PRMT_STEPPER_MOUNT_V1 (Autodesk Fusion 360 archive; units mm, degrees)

design "PRMT_STEPPER_MOUNT_V1" references "23HS30-2904S-EGS50", "17HS13-0404S-MG5", "14HS13-0804S-PG14"
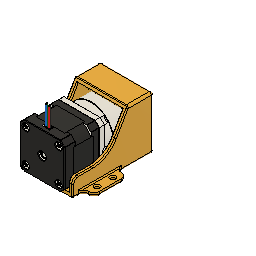
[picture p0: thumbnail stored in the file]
part number: 2026-08-30-19-16-32-664
part number: 2026-09-01-19-58-08-803
parameter "PLT_V" = 42
parameter "PLT_H" = 42
parameter "PLT_HOLE_DIA" = 3.3
parameter "TOL_HOLE_DIA" = 0.2
parameter "PLT_SIDE_H" = 5
parameter "PLT_SIDE_V" = 5
parameter "SHAFT_DIA" = 8
parameter "HEIGTH" = 76
parameter "PLT_HOLE_DIST" = 17.5
parameter "d23" = 5 (= "PLT_SIDE_V")
component_insert "Component Insert1"
component_insert "Component Insert2"
component_insert "Component Insert3"
as_built_joint "As-built1"
as_built_joint "As-built2"
position "Position1"
work_plane "WorkPlane1" AlongDistance 0 ExtraOffset 0
sketch "Sketch1" plane through (0, 0, -38.8) normal (0, 0, -1) x axis (-1, 0, 0)
  curve K1 (23.57, 21.92) -> (23.57, 21.92)
  curve K2 (-23.57, 21.92) -> (-23.57, 21.92)
  curve K3 (-23.57, -25.22) -> (-23.57, -25.22)
  curve K4 (23.57, -25.22) -> (23.57, -25.22)
  line L1 (-25, 25) -> (25, 25)
  line L2 (-25, -25) -> (-25, 25)
  line L3 (25, -25) -> (-25, -25)
  line L4 (25, 25) -> (25, -25)
  line L5 (-25, -25) -> (25, 25)
  line L6 (25, -25) -> (-25, 25)
  circle C1 centre (-17.5, 0) radius 1.75
  circle C2 centre (-23.57, 23.57) radius 1.65
  circle C3 centre (23.57, 23.57) radius 1.65
  circle C4 centre (-23.57, -23.57) radius 1.65
  circle C5 centre (0, 0) radius 8.75
  circle C6 centre (0, 0) radius 1.25
  point P1 (0, 0)
  point P2 (0, 0)
  point P19 (0, 0)
  point P20 (0, 0)
  point P3 (-17.5, 0)
  point P15 (25, 25)
  point P16 (-25, 25)
  point P18 (25, -25)
  point P22 (0, 0)
  coincident P1 P2
  horizontal L1
  perpendicular L1 L2
  parallel L1 L3
  parallel L2 L4
  coincident L5 P19
  coincident L6 P19
  coincident P1 P19
  coincident P1 P20
  horizontal P1 P3
  dimension "d3" diameter C1 = 3.5 (= "PLT_HOLE_DIA + TOL_HOLE_DIA")
  dimension "d29" diameter C5 = 17.5 (= "PLT_HOLE_DIST")
  dimension "d51" distance P15 P16 = 50 (= "PLT_H + 8 mm")
  dimension "d52" distance P15 P18 = 50 (= "d51")
  dimension "d53" distance P3 P22 = 17.5 (= "PLT_HOLE_DIST")
extrude "Extrude1" new body sketch "Sketch1" profile of C1 L1 L2 L3 L4 C5 C6 no distance stored from offset 5
shell "Shell1" innerThickness 4
extrude "Extrude2" cut sketch "Sketch1" profile of C5 distance 240
extrude "Extrude3" cut sketch "Sketch1" profile of C1 along normal blind 10 and against normal blind 150
circular_pattern "C-Pattern1" TotalAngle 360
chamfer "Chamfer1" distance 1
sketch "Sketch2" plane through (0, 0, 0) normal (1, 0, 0) x axis (0, 0, -1)
  line L1 (0.7474, -8) -> (19.8, 25)
  line L2 (-125, -8) -> (0.7474, -8)
  line L3 (-32.2, -25) -> (43.8, -25)
  line L4 (43.8, 25) -> (43.8, -25)
  line L5 (19.8, 25) -> (43.8, 25)
  line L6 (43.8, 45) -> (43.8, 25)
  line L7 (-125, 45) -> (43.8, 45)
  line L8 (-125, -8) -> (-125, 45)
  line L9 (-32.2, 25) -> (43.8, 25)
  point P2 (19.8, 25)
  point P8 (43.8, 25)
  point P9 (43.8, 25)
  point P10 (43.8, 45)
  horizontal L2
  horizontal P2 P8
  coincident P8 P9
  perpendicular L5 L6
  perpendicular L6 L7
  vertical L8
  dimension "d37" distance L2 L3 = 17 (= "3 mm + PLT_H / 3")
  dimension "d38" distance P2 L4 = 24 (= "5 mm + HEIGTH / 4")
  dimension "d40" distance P9 P10 = 20
  dimension "d50" angle L1 L9 = 120
extrude "Extrude4" cut sketch "Sketch2" profile of L1 L2 L5 L6 L7 L8 distance 70
fillet "Fillet1" radius 25.3333 (= "HEIGTH / 3")
sketch "Sketch3" plane through (0, -25, 0) normal (0, -1, 0) x axis (1, 0, 0)
  line L1 (25, -43.8) -> (-25, -43.8)
  line L2 (25, 32.2) -> (25, -43.8)
  line L3 (-25, 32.2) -> (25, 32.2)
  line L4 (-25, -43.8) -> (-25, 32.2)
  line L5 (35, -8.4667) -> (-35, -8.4667)
  line L6 (35, 22.2) -> (35, -8.4667)
  line L7 (-35, 22.2) -> (35, 22.2)
  line L8 (-35, -8.4667) -> (-35, 22.2)
  line L9 (35, 22.2) -> (-35, -8.4667)
  line L10 (-35, 22.2) -> (35, -8.4667)
  line L11 (30, -0.4667) -> (-30, -0.4667)
  line L12 (30, 14.2) -> (30, -0.4667)
  line L13 (-30, 14.2) -> (30, 14.2)
  line L14 (-30, -0.4667) -> (-30, 14.2)
  line L15 (30, 14.2) -> (-30, -0.4667)
  line L16 (-30, 14.2) -> (30, -0.4667)
  circle C1 centre (-30, -0.4667) radius 1.65
  circle C2 centre (-30, 14.2) radius 1.65
  circle C3 centre (30, 14.2) radius 1.65
  circle C4 centre (30, -0.4667) radius 1.65
  point P10 (0, 6.8667)
  point P1 (0, 0)
  point P16 (0, 6.8667)
  point P11 (-30, -0.4667)
  point P12 (-30, -0.4667)
  point P15 (-30, 14.2)
  point P17 (-30, 14.2)
  point P14 (30, 14.2)
  point P18 (30, 14.2)
  point P13 (30, -0.4667)
  point P19 (30, -0.4667)
  horizontal L5
  perpendicular L5 L6
  parallel L5 L7
  parallel L6 L8
  coincident L9 P10
  coincident L10 P10
  vertical P1 P10
  horizontal L11
  perpendicular L11 L12
  parallel L11 L13
  parallel L12 L14
  coincident L15 P16
  coincident L16 P16
  coincident P11 P12
  coincident P10 P16
  coincident P15 P17
  coincident P14 P18
  coincident P13 P19
  dimension "d58" distance L4 L8 = 10
  dimension "d59" distance L3 L7 = 10
  dimension "d60" distance L3 P10 = 25.3333 (= "HEIGTH / 3")
  dimension "d61" diameter C1 = 3.3 (= "PLT_HOLE_DIA")
  dimension "d62" diameter C4 = 3.3 (= "d61")
  dimension "d63" diameter C2 = 3.3 (= "d61")
  dimension "d64" diameter C3 = 3.3 (= "d63")
  dimension "d65" distance L8 P12 = 5
  dimension "d66" distance L5 P11 = 8
extrude "Extrude5" add sketch "Sketch3" profile of L2 L4 L5 L6 L7 L8 C1 C2 C3 C4 to an object
fillet "Fillet2" radius 5
chamfer "Chamfer2" distance 1
fillet "Fillet3" radius 1
fillet "Fillet4" radius 5
fillet "Fillet5" radius 2
fillet "Fillet6" radius 1
component_from_bodies "Body->Comp"
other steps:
base_feature "Base Feature"
create_component "CreateComponent1"
reparent_decal "ReparentDecal1"
remove_body "RemoveBody1"

design "14HS13-0804S-PG14"
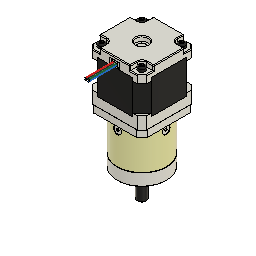
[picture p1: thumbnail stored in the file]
description: STEP AP214
part number: 14HS13-0804S-PG14
base_feature "Base Feature"

design "23HS30-2904S-EGS50"
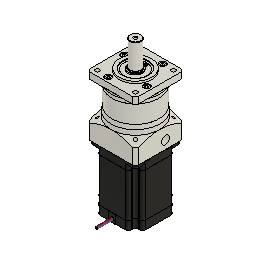
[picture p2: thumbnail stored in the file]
description: STEP AP214
part number: 23HS30-2904S-EGS50
description: Part Number
part number: 23HS30-2904S
part number: EGS23-G50
base_feature "Base Feature1"
base_feature "Base Feature1"
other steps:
create_component "CreateComponent1"
create_component "CreateComponent2"

design "17HS13-0404S-MG5"
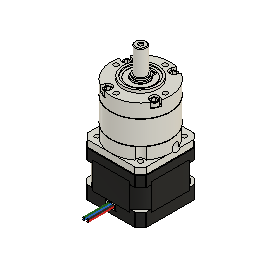
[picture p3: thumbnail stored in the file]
description: STEP AP214
part number: 17HS13-0404S-MG5
description: Part Number
part number: 17HS13-0404S1
part number: MG17 output
part number: 42GN Input flange
part number: 6801
part number: Input shaft
part number: M3 hexagon socket screw head
part number: MG17-G5
base_feature "Base Feature1"
base_feature "Base Feature1"
base_feature "Base Feature1"
base_feature "Base Feature1"
base_feature "Base Feature1"
base_feature "Base Feature1"
base_feature "Base Feature1"
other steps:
create_component "CreateComponent1"
create_component "CreateComponent2"
create_component "CreateComponent1"
create_component "CreateComponent2"
create_component "CreateComponent3"
create_component "CreateComponent4"
create_component "CreateComponent5"
create_component "CreateComponent6"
